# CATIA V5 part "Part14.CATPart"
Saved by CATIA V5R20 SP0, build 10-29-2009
Part number: 9TS1606M6
Revision: ANY
Definition: UNKNOWN
Nomenclature: 9TS1606M6
Source: Unknown
Bounding box of the stored display mesh (mm): x -8 to 8, y -8 to 8, z 0 to 6
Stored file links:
  C:\Users\Utente\Desktop\IO LAVORO\3D X SITO CF\CUMSA\3D files GR\GR 222826-15\Part14.CATPart
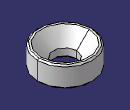
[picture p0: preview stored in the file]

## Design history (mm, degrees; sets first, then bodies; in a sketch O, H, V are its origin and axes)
Body1 "Chaflán1" (main body)
  Solid1: solid without history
